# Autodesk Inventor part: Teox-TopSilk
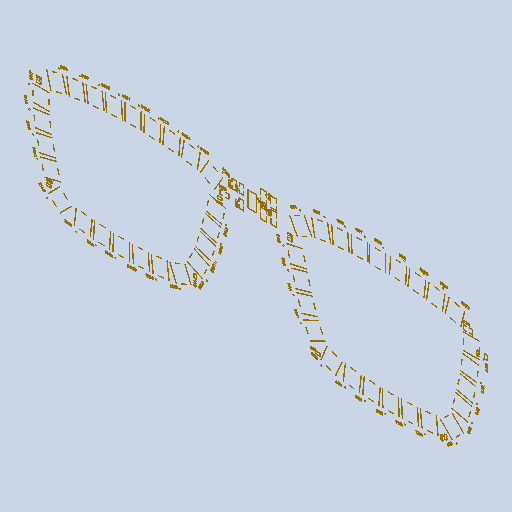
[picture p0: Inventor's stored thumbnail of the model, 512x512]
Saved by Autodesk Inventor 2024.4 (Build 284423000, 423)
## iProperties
Created: 2025-05
Part Number: Teox-TopSilk
Material: Generic
Document SubType Name: Modeling
Designer: AdminForWorker
Density: 1 g/cm^3
Appearance: Default
Title: Teox-TopSilk
Author: AdminForWorker
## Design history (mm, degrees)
feature "Composite1"
body "Srf1"
